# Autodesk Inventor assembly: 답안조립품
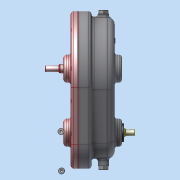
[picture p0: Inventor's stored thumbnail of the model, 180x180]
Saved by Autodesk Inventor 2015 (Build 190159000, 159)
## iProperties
Created: 2024-05
Part Number: 답안조립품
Document SubType Name: Assembly
Designer: Administrator
Author: Administrator
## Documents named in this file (12)
- C:\Users\Administrator\Desktop\740504V1005\답안조립품.iam
- C:\Users\Administrator\Desktop\740504V1005\본체.ipt
- C:\Users\Administrator\Desktop\740504V1005\상단 축.ipt
- C:\Users\Administrator\Desktop\740504V1005\하단 축.ipt
- C:\Users\Administrator\Desktop\740504V1005\오일리스 부시.ipt
- C:\Users\Administrator\Desktop\740504V1005\평행키 5x5x12.ipt
- C:\Users\Administrator\Desktop\740504V1005\스퍼기어A.ipt
- C:\Users\Administrator\Desktop\740504V1005\스퍼기어B.ipt
- C:\Users\Administrator\Desktop\740504V1005\커버.ipt
- C:\Users\Administrator\Desktop\740504V1005\오일 실 10 20 4.ipt
- C:\Users\Administrator\Desktop\740504V1005\육각 머리 볼트  M6x0.75x6.ipt
- C:\Users\Administrator\Desktop\740504V1005\육각 소켓 머리 볼트 M4x10.ipt
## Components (1 placed, 1 different names)
1. 하단 축:1
